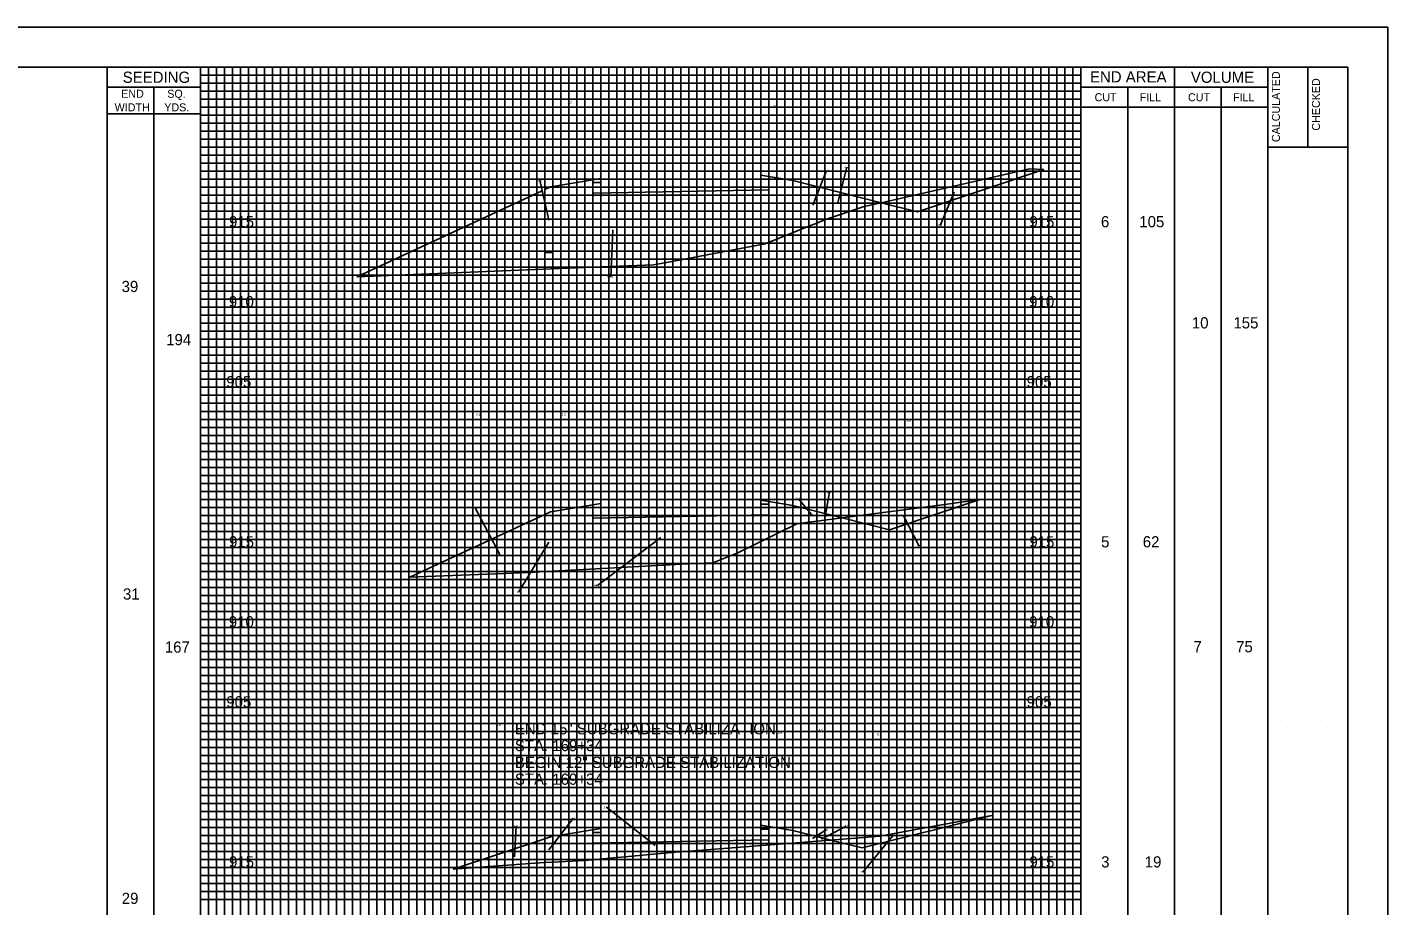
# Model space of a CAD drawing. Extents: x -73 to 160, y -2 to 1877.
# Drawn here: x 75 to 160, y 512.6 to 567.5 of the extents above; entities that cross this region are included whole.
import ezdxf

# ---------------------------------------------------------------- set-up
doc = ezdxf.new("R2010")
doc.units = 0
for name, color, linetype in [('DR_P_Flood_Boundary', 7, 'Continuous'), ('GK_Cells', 7, 'Continuous'), ('RD_X_Fence', 7, 'Continuous'), ('TX_X_5', 7, 'Continuous'), ('UT_P_Water_Cells', 7, 'Continuous'), ('XS_P_Pavt_Surface', 7, 'Continuous'), ('XS_X_Ground_Line', 7, 'Continuous')]:
    doc.layers.add(name, color=color, linetype=linetype)

msp = doc.modelspace()

# ---------------------------------------------------------------- linework, layer by layer
at = {"layer": 'DR_P_Flood_Boundary'}
for p, q in [((90.832, 460), (90.832, 565)), ((95.832, 460), (95.832, 565)), ((100.832, 460), (100.832, 565)), ((105.832, 460), (105.832, 565)), ((110.832, 460), (110.832, 565)), ((115.832, 460), (115.832, 565)), ((120.832, 460), (120.832, 565)), ((125.832, 460), (125.832, 565)), ((130.832, 460), (130.832, 565)), ((135.832, 460), (135.832, 565)), ((85.832, 560), (140.832, 560)), ((85.832, 555), (140.832, 555)), ((85.832, 550), (140.832, 550)), ((85.832, 545), (140.832, 545)), ((85.832, 540), (140.832, 540)), ((85.832, 535), (140.832, 535)), ((85.832, 530), (140.832, 530)), ((85.832, 525), (140.832, 525)), ((85.832, 520), (140.832, 520)), ((85.832, 515), (140.832, 515))]:
    msp.add_line(p, q, dxfattribs=at)
at = {"layer": 'GK_Cells'}
for p, q in [((152.5, 460), (152.5, 565)), ((155, 565), (155, 560)), ((152.5, 560), (157.5, 560))]:
    msp.add_line(p, q, dxfattribs=at)
msp.add_lwpolyline([(0, 565), (157.5, 565), (157.5, 460), (0, 460)], close=True, dxfattribs=at)
at = {"layer": 'RD_X_Fence'}
for p, q in [((124.077, 556.382), (124.942, 558.543)), ((124.077, 556.382), (124.942, 558.543)), ((124.077, 556.382), (124.942, 558.543)), ((124.077, 556.382), (124.942, 558.543)), ((125.631, 556.472), (126.203, 558.752)), ((130.619, 555.97), (138.516, 558.602)), ((107.585, 555.448), (107.029, 557.943)), ((110.832, 558.05), (107.832, 557.55)), ((110.332, 557.79), (110.832, 557.8)), ((110.332, 557.123), (110.332, 557.79)), ((122.832, 557.917), (120.832, 558.25)), ((120.832, 558), (121.332, 558.01)), ((121.332, 558.01), (121.332, 557.343)), ((123.832, 557.667), (122.832, 557.917)), ((124.332, 557.542), (123.832, 557.667)), ((123.832, 557.667), (123.832, 555.06)), ((123.832, 555.06), (123.832, 557.667)), ((107.175, 557.285), (95.595, 551.9)), ((107.332, 556.579), (107.175, 557.285)), ((107.698, 557.528), (107.332, 557.358)), ((107.332, 557.358), (107.332, 553.427)), ((107.832, 557.55), (107.698, 557.528)), ((107.832, 553.427), (107.832, 557.55)), ((107.832, 557.55), (107.832, 553.427)), ((121.332, 557.343), (110.332, 557.123)), ((128.353, 556.537), (124.332, 557.542)), ((124.332, 557.542), (124.332, 555.26)), ((124.332, 555.26), (124.332, 557.542)), ((132.916, 557.197), (132.037, 555.108)), ((107.332, 553.427), (107.332, 556.579)), ((128.353, 556.537), (130.619, 555.97)), ((123.832, 555.06), (124.332, 555.26)), ((111.585, 554.839), (111.457, 551.889)), ((124.859, 536.904), (125.124, 538.465)), ((104.524, 534.554), (102.989, 537.48)), ((107.698, 537.221), (107.332, 537.051)), ((107.832, 537.243), (107.698, 537.221)), ((110.832, 537.743), (107.832, 537.243)), ((107.832, 533.516), (107.832, 537.243)), ((107.832, 537.243), (107.832, 533.516)), ((110.332, 537.483), (110.832, 537.493)), ((110.332, 536.817), (110.332, 537.483)), ((122.832, 537.61), (120.832, 537.943)), ((120.832, 537.693), (121.332, 537.703)), ((121.332, 537.703), (121.332, 537.037)), ((123.832, 537.36), (122.832, 537.61)), ((124.071, 536.951), (123.183, 538.035)), ((123.832, 536.571), (123.832, 537.36)), ((124.332, 537.235), (123.832, 537.36)), ((123.832, 537.36), (123.832, 536.571)), ((124.332, 536.636), (124.332, 537.235)), ((125.911, 536.84), (124.332, 537.235)), ((124.332, 537.235), (124.332, 536.636)), ((128.872, 536.1), (134.517, 537.982)), ((107.332, 537.051), (98.909, 533.134)), ((107.332, 533.488), (107.332, 537.051)), ((107.332, 537.051), (107.332, 533.488)), ((121.332, 537.037), (110.332, 536.817)), ((123.832, 536.571), (124.332, 536.636)), ((124.332, 536.636), (125.911, 536.84)), ((125.911, 536.84), (128.872, 536.1)), ((129.749, 536.965), (130.723, 535.077)), ((114.583, 535.624), (110.619, 532.622)), ((107.585, 535.332), (105.719, 532.225)), ((107.332, 533.488), (107.832, 533.516)), ((114.237, 516.368), (111.189, 518.762)), ((107.586, 516.096), (109.116, 518.052)), ((127.166, 516.22), (135.254, 518.242)), ((105.433, 515.668), (105.537, 517.58)), ((107.698, 516.914), (107.332, 516.792)), ((107.832, 516.937), (107.698, 516.914)), ((108.305, 517.015), (107.832, 516.411)), ((107.832, 515.332), (107.832, 516.937)), ((110.832, 517.437), (108.305, 517.015)), ((110.332, 517.177), (110.832, 517.187)), ((110.332, 516.51), (110.332, 517.177)), ((122.832, 517.303), (120.832, 517.637)), ((120.832, 517.387), (121.332, 517.397)), ((121.332, 517.397), (121.332, 516.73)), ((123.832, 517.053), (122.832, 517.303)), ((123.832, 516.608), (123.832, 517.053)), ((124.332, 516.928), (123.832, 517.053)), ((123.832, 517.053), (123.832, 516.608)), ((124.064, 516.811), (124.928, 517.364)), ((124.332, 516.647), (124.332, 516.928)), ((125.187, 516.715), (124.332, 516.928)), ((124.332, 516.928), (124.332, 516.647)), ((124.617, 516.763), (126.169, 517.574)), ((129.057, 516.962), (127.198, 514.716)), ((107.332, 516.792), (101.616, 514.887)), ((107.332, 515.304), (107.332, 516.792)), ((107.332, 516.792), (107.332, 515.304)), ((107.832, 516.411), (107.832, 515.332)), ((121.332, 516.73), (110.332, 516.51)), ((123.832, 516.608), (124.332, 516.647)), ((124.332, 516.647), (125.187, 516.715)), ((125.187, 516.715), (127.166, 516.22)), ((107.332, 515.304), (107.832, 515.332))]:
    msp.add_line(p, q, dxfattribs=at)
for points in [[(138.516, 558.602), (137.617, 558.645), (128.353, 556.537)], [(110.832, 557.8), (110.832, 557.946), (110.832, 558.05)], [(120.832, 558.25), (120.832, 558.146), (120.832, 558)], [(124.332, 555.26), (124.877, 555.478), (127.293, 556.296), (128.353, 556.537)], [(95.595, 551.9), (109.26, 552.459), (114.156, 552.654), (115.832, 552.971), (121.111, 553.971), (123.832, 555.06)], [(107.332, 553.427), (107.409, 553.427), (107.415, 553.427), (107.419, 553.427), (107.46, 553.427), (107.468, 553.427), (107.478, 553.427), (107.497, 553.427), (107.503, 553.427), (107.507, 553.427), (107.507, 553.427), (107.617, 553.427), (107.619, 553.427), (107.63, 553.427), (107.635, 553.427), (107.658, 553.427), (107.677, 553.427), (107.682, 553.427), (107.686, 553.427), (107.832, 553.427)], [(107.832, 553.427), (107.617, 553.427), (107.46, 553.427), (107.332, 553.427)], [(110.832, 537.493), (110.832, 537.639), (110.832, 537.743)], [(120.832, 537.943), (120.832, 537.839), (120.832, 537.693)], [(134.517, 537.982), (132.175, 537.653), (125.911, 536.84)], [(107.832, 533.516), (115.521, 533.939), (115.833, 533.953), (117.836, 534.044), (119.398, 534.663), (123.075, 536.473), (123.832, 536.571)], [(98.909, 533.134), (106.409, 533.437), (107.332, 533.488)], [(135.254, 518.242), (128.275, 516.959), (125.187, 516.715)], [(110.832, 517.187), (110.832, 517.332), (110.832, 517.437)], [(120.832, 517.637), (120.832, 517.532), (120.832, 517.387)], [(107.832, 515.332), (109.845, 515.445), (115.502, 515.95), (115.832, 515.976), (123.832, 516.608)], [(101.616, 514.887), (106.133, 515.237), (107.332, 515.304)]]:
    msp.add_lwpolyline(points, dxfattribs=at)
at = {"layer": 'TX_X_5'}
msp.add_lwpolyline([(-10, 457.5), (160, 457.5), (160, 567.5), (-10, 567.5)], close=True, dxfattribs=at)
at = {"layer": 'UT_P_Water_Cells'}
for p, q in [((85.832, 564.5), (140.832, 564.5)), ((86.332, 460), (86.332, 565)), ((86.832, 460), (86.832, 565)), ((87.332, 460), (87.332, 565)), ((87.832, 460), (87.832, 565)), ((88.332, 460), (88.332, 565)), ((88.832, 460), (88.832, 565)), ((89.332, 460), (89.332, 565)), ((89.832, 460), (89.832, 565)), ((90.332, 460), (90.332, 565)), ((91.332, 460), (91.332, 565)), ((91.832, 460), (91.832, 565)), ((92.332, 460), (92.332, 565)), ((92.832, 460), (92.832, 565)), ((93.332, 460), (93.332, 565)), ((93.832, 460), (93.832, 565)), ((94.332, 460), (94.332, 565)), ((94.832, 460), (94.832, 565)), ((95.332, 460), (95.332, 565)), ((96.332, 460), (96.332, 565)), ((96.832, 460), (96.832, 565)), ((97.332, 460), (97.332, 565)), ((97.832, 460), (97.832, 565)), ((98.332, 460), (98.332, 565)), ((98.832, 460), (98.832, 565)), ((99.332, 460), (99.332, 565)), ((99.832, 460), (99.832, 565)), ((100.332, 460), (100.332, 565)), ((101.332, 460), (101.332, 565)), ((101.832, 460), (101.832, 565)), ((102.332, 460), (102.332, 565)), ((102.832, 460), (102.832, 565)), ((103.332, 460), (103.332, 565)), ((103.832, 460), (103.832, 565)), ((104.332, 460), (104.332, 565)), ((104.832, 460), (104.832, 565)), ((105.332, 460), (105.332, 565)), ((106.332, 460), (106.332, 565)), ((106.832, 460), (106.832, 565)), ((107.332, 460), (107.332, 565)), ((107.832, 460), (107.832, 565)), ((108.332, 460), (108.332, 565)), ((108.832, 460), (108.832, 565)), ((109.332, 460), (109.332, 565)), ((109.832, 460), (109.832, 565)), ((110.332, 460), (110.332, 565)), ((111.332, 460), (111.332, 565)), ((111.832, 460), (111.832, 565)), ((112.332, 460), (112.332, 565)), ((112.832, 460), (112.832, 565)), ((113.332, 460), (113.332, 565)), ((113.832, 460), (113.832, 565)), ((114.332, 460), (114.332, 565)), ((114.832, 460), (114.832, 565)), ((115.332, 460), (115.332, 565)), ((116.332, 460), (116.332, 565)), ((116.832, 460), (116.832, 565)), ((117.332, 460), (117.332, 565)), ((117.832, 460), (117.832, 565)), ((118.332, 460), (118.332, 565)), ((118.832, 460), (118.832, 565)), ((119.332, 460), (119.332, 565)), ((119.832, 460), (119.832, 565)), ((120.332, 460), (120.332, 565)), ((121.332, 460), (121.332, 565)), ((121.832, 460), (121.832, 565)), ((122.332, 460), (122.332, 565)), ((122.832, 460), (122.832, 565)), ((123.332, 460), (123.332, 565)), ((123.832, 460), (123.832, 565)), ((124.332, 460), (124.332, 565)), ((124.832, 460), (124.832, 565)), ((125.332, 460), (125.332, 565)), ((126.332, 460), (126.332, 565)), ((126.832, 460), (126.832, 565)), ((127.332, 460), (127.332, 565)), ((127.832, 460), (127.832, 565)), ((128.332, 460), (128.332, 565)), ((128.832, 460), (128.832, 565)), ((129.332, 460), (129.332, 565)), ((129.832, 460), (129.832, 565)), ((130.332, 460), (130.332, 565)), ((131.332, 460), (131.332, 565)), ((131.832, 460), (131.832, 565)), ((132.332, 460), (132.332, 565)), ((132.832, 460), (132.832, 565)), ((133.332, 460), (133.332, 565)), ((133.832, 460), (133.832, 565)), ((134.332, 460), (134.332, 565)), ((134.832, 460), (134.832, 565)), ((135.332, 460), (135.332, 565)), ((136.332, 460), (136.332, 565)), ((136.832, 460), (136.832, 565)), ((137.332, 460), (137.332, 565)), ((137.832, 460), (137.832, 565)), ((138.332, 460), (138.332, 565)), ((138.832, 460), (138.832, 565)), ((139.332, 460), (139.332, 565)), ((139.832, 460), (139.832, 565)), ((140.332, 460), (140.332, 565)), ((85.832, 564), (140.832, 564)), ((85.832, 563.5), (140.832, 563.5)), ((85.832, 563), (140.832, 563)), ((85.832, 562.5), (140.832, 562.5)), ((85.832, 562), (140.832, 562)), ((85.832, 561.5), (140.832, 561.5)), ((85.832, 561), (140.832, 561)), ((85.832, 560.5), (140.832, 560.5)), ((85.832, 559.5), (140.832, 559.5)), ((85.832, 559), (140.832, 559)), ((85.832, 558.5), (140.832, 558.5)), ((85.832, 558), (140.832, 558)), ((85.832, 557.5), (140.832, 557.5)), ((85.832, 557), (140.832, 557)), ((85.832, 556.5), (140.832, 556.5)), ((85.832, 556), (140.832, 556)), ((85.832, 555.5), (140.832, 555.5)), ((85.832, 554.5), (140.832, 554.5)), ((85.832, 554), (140.832, 554)), ((85.832, 553.5), (140.832, 553.5)), ((85.832, 553), (140.832, 553)), ((85.832, 552.5), (140.832, 552.5)), ((85.832, 552), (140.832, 552)), ((85.832, 551.5), (140.832, 551.5)), ((85.832, 551), (140.832, 551)), ((85.832, 550.5), (140.832, 550.5)), ((85.832, 549.5), (140.832, 549.5)), ((85.832, 549), (140.832, 549)), ((85.832, 548.5), (140.832, 548.5)), ((85.832, 548), (140.832, 548)), ((85.832, 547.5), (140.832, 547.5)), ((85.832, 547), (140.832, 547)), ((85.832, 546.5), (140.832, 546.5)), ((85.832, 546), (140.832, 546)), ((85.832, 545.5), (140.832, 545.5)), ((85.832, 544.5), (140.832, 544.5)), ((85.832, 544), (140.832, 544)), ((85.832, 543.5), (140.832, 543.5)), ((85.832, 543), (140.832, 543)), ((85.832, 542.5), (140.832, 542.5)), ((85.832, 542), (140.832, 542)), ((85.832, 541.5), (140.832, 541.5)), ((85.832, 541), (140.832, 541)), ((85.832, 540.5), (140.832, 540.5)), ((85.832, 539.5), (140.832, 539.5)), ((85.832, 539), (140.832, 539)), ((85.832, 538.5), (140.832, 538.5)), ((85.832, 538), (140.832, 538)), ((85.832, 537.5), (140.832, 537.5)), ((85.832, 537), (140.832, 537)), ((85.832, 536.5), (140.832, 536.5)), ((85.832, 536), (140.832, 536)), ((85.832, 535.5), (140.832, 535.5)), ((85.832, 534.5), (140.832, 534.5)), ((85.832, 534), (140.832, 534)), ((85.832, 533.5), (140.832, 533.5)), ((85.832, 533), (140.832, 533)), ((85.832, 532.5), (140.832, 532.5)), ((85.832, 532), (140.832, 532)), ((85.832, 531.5), (140.832, 531.5)), ((85.832, 531), (140.832, 531)), ((85.832, 530.5), (140.832, 530.5)), ((85.832, 529.5), (140.832, 529.5)), ((85.832, 529), (140.832, 529)), ((85.832, 528.5), (140.832, 528.5)), ((85.832, 528), (140.832, 528)), ((85.832, 527.5), (140.832, 527.5)), ((85.832, 527), (140.832, 527)), ((85.832, 526.5), (140.832, 526.5)), ((85.832, 526), (140.832, 526)), ((85.832, 525.5), (140.832, 525.5)), ((85.832, 524.5), (140.832, 524.5)), ((85.832, 524), (140.832, 524)), ((85.832, 523.5), (140.832, 523.5)), ((85.832, 523), (140.832, 523)), ((85.832, 522.5), (140.832, 522.5)), ((85.832, 522), (140.832, 522)), ((85.832, 521.5), (140.832, 521.5)), ((85.832, 521), (140.832, 521)), ((85.832, 520.5), (140.832, 520.5)), ((85.832, 519.5), (140.832, 519.5)), ((85.832, 519), (140.832, 519)), ((85.832, 518.5), (140.832, 518.5)), ((85.832, 518), (140.832, 518)), ((85.832, 517.5), (140.832, 517.5)), ((85.832, 517), (140.832, 517)), ((85.832, 516.5), (140.832, 516.5)), ((85.832, 516), (140.832, 516)), ((85.832, 515.5), (140.832, 515.5)), ((85.832, 514.5), (140.832, 514.5)), ((85.832, 514), (140.832, 514)), ((85.832, 513.5), (140.832, 513.5)), ((85.832, 513), (140.832, 513))]:
    msp.add_line(p, q, dxfattribs=at)
at = {"layer": 'XS_X_Ground_Line'}
for p, q in [((80, 460), (80, 565)), ((85.832, 460), (85.832, 565)), ((140.832, 460), (140.832, 565)), ((146.667, 460), (146.667, 565)), ((85.832, 563.75), (80, 563.75)), ((82.916, 460), (82.916, 563.75)), ((140.832, 563.75), (152.5, 563.75)), ((143.75, 460), (143.75, 563.75)), ((149.583, 460), (149.583, 563.75)), ((85.832, 562.083), (80, 562.083)), ((140.832, 562.5), (152.5, 562.5)), ((154.6, 562.518), (154.6, 562.518)), ((157.1, 562.518), (157.1, 562.518)), ((153.75, 523.75), (153.75, 523.75)), ((156.258, 523.75), (156.258, 523.75))]:
    msp.add_line(p, q, dxfattribs=at)

# ---------------------------------------------------------------- texts
at = {"layer": 'RD_X_Fence'}
for s, p in [('13.3', (102.462, 562.919)), ('3.2', (108.764, 562.729)), ('2.0', (121.595, 562.507)), ('8.0', (126.721, 562.422)), ('8.3', (132.484, 562.482)), ('1.2', (124.824, 558.473)), ('4.4', (126.057, 558.682)), ('2.0', (106.878, 557.873)), ('6.4', (131.89, 555.038)), ('97.4', (111.251, 551.819)), ('9.8', (103.052, 543.231)), ('3.2', (108.385, 543.231)), ('2.0', (122.035, 542.915)), ('6.2', (126.193, 542.89)), ('5.9', (129.963, 542.839)), ('0.3', (123.03, 537.965)), ('0.5', (124.972, 538.395)), ('15.1', (102.836, 537.41)), ('4.8', (130.576, 535.007)), ('1.8', (105.6, 532.155)), ('44.0', (110.405, 532.552)), ('6.4', (104.31, 523.833)), ('3.2', (108.308, 523.691)), ('4.5', (124.442, 523.52)), ('2.0', (121.885, 523.342)), ('8.3', (128.094, 523.254)), ('13.7', (111.008, 518.692)), ('4.2', (105.391, 517.51)), ('0.8', (108.963, 517.982)), ('0.2', (124.776, 517.294)), ('0.1', (126.043, 517.504)), ('2.9', (127.053, 514.646))]:
    msp.add_text(s, height=0.14, dxfattribs=at).set_placement(p)
at = {"layer": 'XS_P_Pavt_Surface'}
for s, p in [('915', (87.609, 555)), ('915', (137.609, 555)), ('6', (142.081, 555)), ('105', (144.476, 555)), ('39', (80.896, 550.951)), ('910', (87.598, 550)), ('910', (137.598, 550)), ('10', (147.76, 548.681)), ('155', (150.356, 548.681)), ('194', (83.682, 547.634)), ('905', (87.438, 545)), ('905', (137.438, 545)), ('915', (87.609, 535)), ('915', (137.609, 535)), ('5', (142.09, 535)), ('62', (144.693, 535)), ('31', (80.981, 531.739)), ('910', (87.598, 530)), ('910', (137.598, 530)), ('167', (83.597, 528.422)), ('7', (147.861, 528.446)), ('75', (150.526, 528.446)), ('905', (87.438, 525)), ('905', (137.438, 525)), ('END 15" SUBGRADE STABILIZATION', (105.467, 523.318)), ('STA. 169+34', (105.467, 522.268)), ('BEGIN 12" SUBGRADE STABILIZATION', (105.467, 521.218)), ('STA. 169+34', (105.467, 520.168)), ('915', (87.609, 515)), ('915', (137.609, 515)), ('3', (142.095, 515)), ('19', (144.815, 515)), ('29', (80.907, 512.723))]:
    msp.add_text(s, height=0.7, dxfattribs=at).set_placement(p)
at = {"layer": 'XS_X_Ground_Line'}
for s, height, p in [('SEEDING', 0.7, (80.964, 564.025)), ('END AREA', 0.7, (141.394, 564.047)), ('VOLUME', 0.7, (147.698, 564.025)), ('END', 0.5, (80.87, 563.092)), ('SQ.', 0.5, (83.748, 563.092)), ('WIDTH', 0.5, (80.462, 562.242)), ('YDS.', 0.5, (83.563, 562.242)), ('CUT', 0.5, (141.683, 562.875)), ('FILL', 0.5, (144.502, 562.875)), ('CUT', 0.5, (147.517, 562.875)), ('FILL', 0.5, (150.335, 562.875))]:
    msp.add_text(s, height=height, dxfattribs=at).set_placement(p)
for s, p in [('CALCULATED', (153.262, 560.323)), ('CHECKED', (155.762, 561.04))]:
    msp.add_text(s, height=0.5, rotation=90, dxfattribs=at).set_placement(p)

doc.saveas('drawing.dxf')
